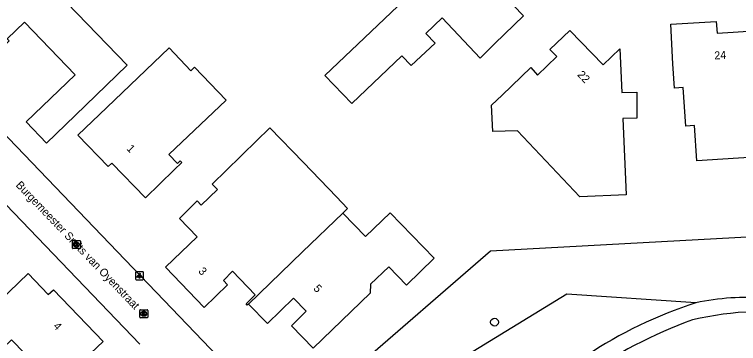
# Model space of a CAD drawing. Extents: x 159503 to 160347, y 382525 to 383272.
# Drawn here: x 159893.2 to 159983.7, y 382910.4 to 382951.5 of the extents above; entities that cross this region are included whole.
import ezdxf

# ---------------------------------------------------------------- set-up
doc = ezdxf.new("R2010")
doc.units = 0
for name, color, linetype in [('IMGEO_Boom', 7, 'Continuous'), ('IMGEO_Groenvoorziening', 7, 'Continuous'), ('IMGEO_Kolk', 7, 'Continuous'), ('IMGEO_Lichtpunt', 7, 'Continuous'), ('IMGEO_Openbare_ruimte_label', 7, 'Continuous'), ('IMGEO_Pand', 7, 'Continuous'), ('IMGEO_Pand_nummerreeks', 7, 'Continuous'), ('IMGEO_Rijbaan_lokaal_open', 7, 'Continuous'), ('IMGEO_Voetpad_halfverhard', 7, 'Continuous')]:
    doc.layers.add(name, color=color, linetype=linetype)

msp = doc.modelspace()

# ---------------------------------------------------------------- linework, layer by layer
at = {"layer": 'IMGEO_Boom'}
msp.add_circle((159953.21, 382913.043), 0.489, dxfattribs=at)
at = {"layer": 'IMGEO_Groenvoorziening'}
for points in [[(159935.493, 382907.023), (159952.688, 382921.969), (160000, 382924.568), (160007.956, 382925.066), (160009.503, 382926.949)], [(159978.374, 382915.464), (159962.238, 382916.541), (159939.597, 382902.666)]]:
    msp.add_lwpolyline(points, dxfattribs=at)
at = {"layer": 'IMGEO_Kolk'}
for p, q in [((159900.464, 382922.318), (159900.464, 382923.17)), ((159900.539, 382923.244), (159901.391, 382923.244)), ((159900.952, 382923.024), (159900.977, 382923.024)), ((159901.465, 382923.17), (159901.465, 382922.318)), ((159901.391, 382922.244), (159900.539, 382922.244)), ((159900.975, 382922.464), (159900.95, 382922.464)), ((159908.882, 382913.672), (159908.882, 382914.524)), ((159908.957, 382914.598), (159909.809, 382914.598)), ((159909.37, 382914.378), (159909.395, 382914.378)), ((159909.883, 382914.524), (159909.883, 382913.672)), ((159909.809, 382913.598), (159908.957, 382913.598)), ((159909.393, 382913.818), (159909.368, 382913.818))]:
    msp.add_line(p, q, dxfattribs=at)
for points in [[(159900.464, 382922.318), (159900.464, 382923.17)], [(159900.539, 382923.244), (159901.391, 382923.244)], [(159901.465, 382923.17), (159901.465, 382922.318)], [(159901.391, 382922.244), (159900.539, 382922.244)], [(159900.785, 382922.944), (159900.908, 382922.944), (159900.908, 382922.793), (159901.038, 382922.944), (159901.202, 382922.944), (159901.056, 382922.793), (159901.209, 382922.544), (159901.057, 382922.544), (159900.972, 382922.708), (159900.908, 382922.641), (159900.908, 382922.544), (159900.785, 382922.544), (159900.785, 382922.944)], [(159908.882, 382913.672), (159908.882, 382914.524)], [(159908.957, 382914.598), (159909.809, 382914.598)], [(159909.203, 382914.298), (159909.326, 382914.298), (159909.326, 382914.147), (159909.456, 382914.298), (159909.62, 382914.298), (159909.474, 382914.147), (159909.627, 382913.898), (159909.475, 382913.898), (159909.39, 382914.062), (159909.326, 382913.995), (159909.326, 382913.898), (159909.203, 382913.898), (159909.203, 382914.298)], [(159909.883, 382914.524), (159909.883, 382913.672)], [(159909.809, 382913.598), (159908.957, 382913.598)]]:
    msp.add_lwpolyline(points, dxfattribs=at)
for centre, start, end in [((159900.541, 382923.168), 91.55205, 178.44795), ((159900.541, 382923.168), 91.55205, 178.44795), ((159901.389, 382923.168), 1.55205, 88.44795), ((159901.389, 382923.168), 1.55205, 88.44795), ((159900.541, 382922.32), 181.55205, 268.44795), ((159900.541, 382922.32), 181.55205, 268.44795), ((159901.389, 382922.32), 271.55205, 358.44795), ((159901.389, 382922.32), 271.55205, 358.44795), ((159908.959, 382914.522), 91.55205, 178.44795), ((159908.959, 382914.522), 91.55205, 178.44795), ((159909.807, 382914.522), 1.55205, 88.44795), ((159909.807, 382914.522), 1.55205, 88.44795), ((159908.959, 382913.674), 181.55205, 268.44795), ((159908.959, 382913.674), 181.55205, 268.44795), ((159909.807, 382913.674), 271.55205, 358.44795), ((159909.807, 382913.674), 271.55205, 358.44795)]:
    msp.add_arc(centre, 0.0765, start, end, dxfattribs=at)
for centre, major_axis, ratio, start_param, end_param in [((159900.951, 382922.744), (-0.387, 0.002), 0.722429, 4.712389, 7.853982), ((159900.976, 382922.744), (-0.39, 0.002), 0.717154, 1.570796, 4.712389), ((159909.369, 382914.098), (-0.387, 0.002), 0.722429, 4.712389, 7.853982), ((159909.394, 382914.098), (-0.39, 0.002), 0.717154, 1.570796, 4.712389)]:
    msp.add_ellipse(centre, major_axis=major_axis, ratio=ratio, start_param=start_param, end_param=end_param, dxfattribs=at)
at = {"layer": 'IMGEO_Lichtpunt'}
for p, q in [((159909.249, 382919.357), (159908.441, 382919.357)), ((159909.249, 382919.357), (159908.441, 382919.357)), ((159908.347, 382919.262), (159908.347, 382918.455)), ((159908.347, 382919.262), (159908.347, 382918.455)), ((159909.343, 382918.455), (159909.343, 382919.262)), ((159909.343, 382918.455), (159909.343, 382919.262)), ((159908.441, 382918.361), (159909.249, 382918.361)), ((159908.441, 382918.361), (159909.249, 382918.361))]:
    msp.add_line(p, q, dxfattribs=at)
for points in [[(159908.721, 382918.926), (159908.76, 382918.898), (159908.572, 382918.636), (159908.534, 382918.663), (159908.721, 382918.926)], [(159908.823, 382918.878), (159908.87, 382918.878), (159908.87, 382918.556), (159908.823, 382918.556), (159908.823, 382918.878)], [(159908.933, 382918.898), (159908.971, 382918.925), (159909.158, 382918.663), (159909.119, 382918.635), (159908.933, 382918.898)]]:
    msp.add_lwpolyline(points, dxfattribs=at)
msp.add_circle((159908.846, 382919.06), 0.0994, dxfattribs=at)
for centre, start, end in [((159908.441, 382919.262), 90, 180), ((159908.441, 382919.262), 90, 180), ((159909.249, 382919.262), 0, 90), ((159909.249, 382919.262), 0, 90), ((159908.441, 382918.455), 180, 270), ((159908.441, 382918.455), 180, 270), ((159909.249, 382918.455), 270, 0), ((159909.249, 382918.455), 270, 360)]:
    msp.add_arc(centre, 0.0946, start, end, dxfattribs=at)
at = {"layer": 'IMGEO_Pand'}
for points in [[(159907.313, 382945.183), (159900.827, 382938.914), (159897.232, 382935.438), (159894.674, 382938.1), (159900.812, 382943.991), (159894.496, 382950.57), (159892.322, 382948.482), (159892.55, 382948.243), (159890.969, 382946.724), (159890.739, 382946.962), (159888.565, 382944.875), (159889.604, 382943.791), (159889.387, 382943.583), (159884.743, 382948.422), (159887.876, 382951.451), (159886.365, 382953.023), (159889.496, 382955.951), (159890.709, 382957.085), (159888.649, 382959.263), (159891.294, 382961.807), (159894.763, 382958.206), (159907.313, 382945.183)], [(159942.81, 382945.14), (159941.604, 382946.347), (159935.384, 382940.398), (159932.01, 382943.902), (159946.063, 382957.311), (159949.681, 382960.761), (159952.057, 382958.267), (159951.15, 382957.329), (159951.983, 382956.452), (159951.534, 382956.005), (159952.617, 382954.913), (159953.046, 382955.323), (159956.844, 382951.362), (159953.255, 382947.882), (159951.397, 382946.081), (159946.683, 382951.101), (159944.62, 382949.165), (159945.781, 382947.93), (159942.81, 382945.14)], [(159989.908, 382939.638), (159990.066, 382935.741), (159986.85, 382935.55), (159986.956, 382933.774), (159978.486, 382933.238), (159978.209, 382937.627), (159977.093, 382937.562), (159976.788, 382942.385), (159975.68, 382942.311), (159975.504, 382945.337), (159975.215, 382950.328), (159980.908, 382950.668), (159981.031, 382949.203), (159983.01, 382949.322), (159986.119, 382949.51), (159986.572, 382941.868), (159989.763, 382942.076)], [(159954.14, 382941.432), (159957.752, 382944.888), (159958.595, 382943.951), (159960.982, 382946.257), (159960.129, 382947.168), (159962.629, 382949.538), (159966.781, 382945.233), (159968.86, 382947.238), (159969.117, 382941.759), (159970.967, 382941.803), (159970.967, 382938.572), (159969.253, 382938.503), (159969.636, 382928.964), (159963.862, 382928.723), (159956.079, 382936.968), (159952.979, 382936.874), (159952.838, 382940.186), (159954.14, 382941.432)], [(159915.253, 382944.482), (159915.74, 382944.944), (159919.667, 382940.805), (159912.531, 382934.033), (159913.599, 382932.908), (159913.94, 382933.232), (159914.148, 382933.015), (159913.185, 382932.084), (159909.591, 382928.607), (159905.373, 382932.912), (159904.95, 382932.507), (159901.14, 382936.451), (159904.755, 382939.906), (159912.537, 382947.342), (159915.253, 382944.482)], [(159922.464, 382915.308), (159922.3, 382915.182), (159922.161, 382915.344), (159923.31, 382916.485), (159920.455, 382919.422), (159919.343, 382918.273), (159919.862, 382917.718), (159916.926, 382914.889), (159912.095, 382919.928), (159916.046, 382923.73), (159913.832, 382926.031), (159916.063, 382928.223), (159916.539, 382927.685), (159918.595, 382929.636), (159917.927, 382930.324), (159921.516, 382933.806), (159921.728, 382934.012), (159925.152, 382937.333), (159929.319, 382933.012), (159933.461, 382928.717), (159934.846, 382927.28), (159934.237, 382926.693)], [(159934.237, 382926.693), (159937.078, 382923.748), (159940.168, 382926.726), (159945.647, 382921.045), (159942.223, 382917.661), (159939.983, 382919.987), (159937.724, 382917.781), (159937.687, 382916.689), (159930.545, 382909.796), (159927.827, 382912.599), (159929.691, 382914.412), (159928.102, 382916.047), (159924.833, 382912.869), (159922.464, 382915.308)], [(159922.464, 382915.308), (159929.208, 382921.845), (159934.237, 382926.693)], [(159898.75, 382900.538), (159897.338, 382901.983), (159899.452, 382904.048), (159897.237, 382906.374), (159896.798, 382905.952), (159895.793, 382906.945), (159896.237, 382907.385), (159892.868, 382910.834), (159884.436, 382902.771), (159882.298, 382900.727), (159879.16, 382904.008), (159881.283, 382906.041), (159891.329, 382915.663), (159894.939, 382919.121), (159897.452, 382916.506), (159898.091, 382917.108), (159904.318, 382910.646), (159901.99, 382908.398), (159902.993, 382907.427), (159900.935, 382905.463), (159902.304, 382904.01)]]:
    msp.add_lwpolyline(points, dxfattribs=at)
at = {"layer": 'IMGEO_Rijbaan_lokaal_open'}
for points in [[(159882.469, 382946.51), (159882.622, 382946.33), (159882.782, 382946.157), (159921.607, 382905.68)], [(159908.873, 382910.281), (159881.307, 382939.023), (159879.787, 382940.656), (159879.627, 382940.809)]]:
    msp.add_lwpolyline(points, dxfattribs=at)
at = {"layer": 'IMGEO_Voetpad_halfverhard'}
for centre, radius, start, end in [((159984.823, 382885.202), 30.941, 85.76316, 102.03041), ((159994.496, 382864.636), 53.323, 107.59863, 124.04292), ((159987.63, 382869.501), 44.911, 82.7755, 102.44082), ((160001.146, 382851.541), 66.023, 110.56391, 124.25603)]:
    msp.add_arc(centre, radius, start, end, dxfattribs=at)

# ---------------------------------------------------------------- texts
at = {"layer": 'IMGEO_Openbare_ruimte_label'}
msp.add_text('Burgemeester Smits van Oyenstraat', height=1, rotation=313.78457, dxfattribs=at).set_placement((159893.321, 382930.119))
at = {"layer": 'IMGEO_Pand_nummerreeks'}
for s, rotation, p in [('24', 3.44348, (159980.694, 382945.897)), ('22', 313.96354, (159963.476, 382943.935)), ('1', 314.41516, (159907.17, 382934.679)), ('3', 313.79095, (159916.138, 382919.351)), ('5', 314.18256, (159930.511, 382917.184)), ('4', 313.93901, (159898.001, 382912.477))]:
    msp.add_text(s, height=1, rotation=rotation, dxfattribs=at).set_placement(p)

doc.saveas('drawing.dxf')
